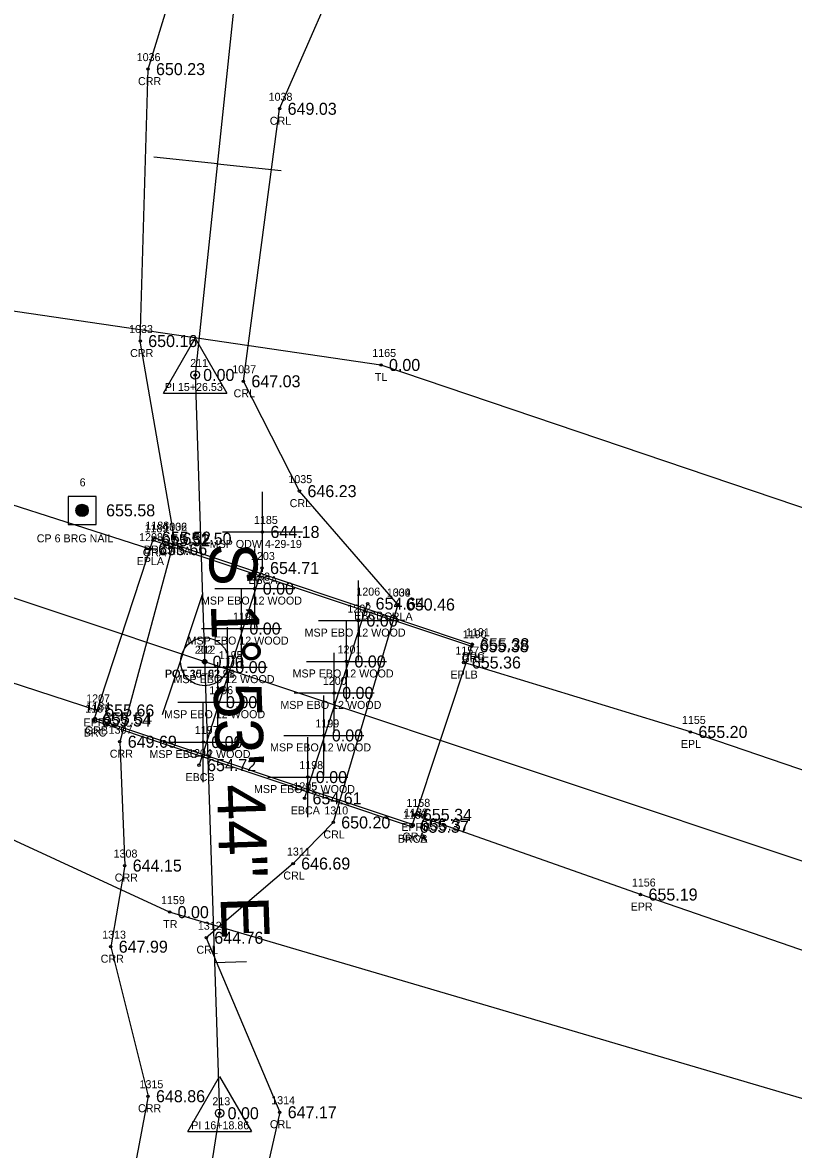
# Model space of a CAD drawing. Extents: x 1655137 to 1657928, y 1003994 to 1005407.
# Drawn here: x 1656349.2 to 1656445.6, y 1004565 to 1004705.8 of the extents above; entities that cross this region are included whole.
import ezdxf

# ---------------------------------------------------------------- set-up
doc = ezdxf.new("R2010")
doc.units = 0
for name, color, linetype in [('RD_EX_Bridge', 7, 'Continuous'), ('RD_EX_Bridge_txCode', 7, 'Continuous'), ('RD_EX_GuardRail', 7, 'Continuous'), ('RD_EX_GuardRail_txCode', 7, 'Continuous'), ('RD_EX_H2O', 7, 'Continuous'), ('RD_EX_H2O_txCode', 7, 'Continuous'), ('RD_EX_Road', 7, 'Continuous'), ('RD_EX_Road_txCode', 7, 'Continuous'), ('RD_EX_TX_Bridge_ELEV', 7, 'Continuous'), ('RD_EX_TX_GuardRail_ELEV', 7, 'Continuous'), ('RD_EX_TX_H2O_ELEV', 7, 'Continuous'), ('RD_EX_TX_Misc_ELEV', 7, 'Continuous'), ('RD_EX_TX_Road_ELEV', 7, 'Continuous'), ('RD_EX_TX_VEG_ELEV', 7, 'Continuous'), ('RD_EX_VEG', 7, 'Continuous'), ('RD_EX_VEG_txCode', 7, 'Continuous'), ('RD_HC_Cl', 7, 'Continuous'), ('RD_HC_Data', 7, 'Continuous'), ('RD_HC_Data_Tic', 7, 'Continuous'), ('RD_HC_Survey', 7, 'Continuous'), ('RD_HC_Survey_ELEV', 7, 'Continuous'), ('RD_HC_Survey_txCode', 7, 'Continuous'), ('RD_HC_txCode', 7, 'Continuous'), ('RD_SMD_Locator', 7, 'Continuous')]:
    doc.layers.add(name, color=color, linetype=linetype)

msp = doc.modelspace()

# ---------------------------------------------------------------- linework, layer by layer
at = {"layer": 'RD_EX_Bridge'}
for p, q in [((1656378.2, 1004630.06), (1656378.2, 1004640.06)), ((1656379.11, 1004637.63), (1656371.24, 1004612.99)), ((1656391.16, 1004626.06), (1656391.16, 1004636.06)), ((1656373.2, 1004635.06), (1656383.2, 1004635.06)), ((1656376.53, 1004625.06), (1656376.53, 1004635.06)), ((1656384.42, 1004608.84), (1656392.31, 1004633.18)), ((1656374.77, 1004620.24), (1656374.77, 1004630.24)), ((1656386.16, 1004631.06), (1656396.16, 1004631.06)), ((1656389.66, 1004620.95), (1656389.66, 1004630.95)), ((1656371.53, 1004630.06), (1656381.53, 1004630.06)), ((1656373.6, 1004615.86), (1656373.6, 1004625.86)), ((1656384.66, 1004625.95), (1656394.66, 1004625.95)), ((1656388.13, 1004617.02), (1656388.13, 1004627.02)), ((1656369.77, 1004625.24), (1656379.77, 1004625.24)), ((1656383.13, 1004622.02), (1656393.13, 1004622.02)), ((1656386.84, 1004611.71), (1656386.84, 1004621.71)), ((1656368.6, 1004620.86), (1656378.6, 1004620.86)), ((1656371.76, 1004610.88), (1656371.76, 1004620.88)), ((1656381.84, 1004616.71), (1656391.84, 1004616.71)), ((1656384.83, 1004606.5), (1656384.83, 1004616.5)), ((1656366.76, 1004615.88), (1656376.76, 1004615.88)), ((1656379.83, 1004611.5), (1656389.83, 1004611.5))]:
    msp.add_line(p, q, dxfattribs=at)
msp.add_lwpolyline([(1656397.81, 1004605.29), (1656358.07, 1004618.57), (1656365.58, 1004641.43), (1656405.39, 1004628.11), (1656397.81, 1004605.29)], dxfattribs=at)
for centre in [(1656378.2, 1004635.06), (1656376.53, 1004630.06), (1656391.16, 1004631.06), (1656389.66, 1004625.95), (1656374.77, 1004625.24), (1656388.13, 1004622.02), (1656373.6, 1004620.86), (1656371.76, 1004615.88), (1656386.84, 1004616.71), (1656384.83, 1004611.5)]:
    msp.add_circle(centre, 0.15, dxfattribs=at)
at = {"layer": 'RD_EX_GuardRail'}
for p, q in [((1656365.47, 1004641.1), (1656405.31, 1004627.86)), ((1656397.94, 1004605.56), (1656358.22, 1004618.83))]:
    msp.add_line(p, q, dxfattribs=at)
at = {"layer": 'RD_EX_H2O'}
for p, q in [((1656379.16, 1004637.14), (1656379.16, 1004647.14)), ((1656374.16, 1004642.14), (1656384.16, 1004642.14))]:
    msp.add_line(p, q, dxfattribs=at)
for points in [[(1656396.09, 1004633.07), (1656383.79, 1004647.24), (1656376.78, 1004660.97), (1656381.31, 1004695.03), (1656390.77, 1004716.64), (1656386.6, 1004756.66), (1656392.47, 1004790.44), (1656395.46, 1004834.73), (1656418.17, 1004880.53), (1656428.48, 1004936.46), (1656416.99, 1004968.14), (1656420.24, 1005011.82), (1656412.2, 1005039.74), (1656428.37, 1005086.9), (1656442.1, 1005137.22), (1656437.49, 1005175.75)], [(1656368.16, 1004641.29), (1656363.88, 1004666), (1656364.85, 1004699.99), (1656373.08, 1004726.71), (1656370.55, 1004754.49), (1656376.9, 1004793.18), (1656381.94, 1004832.3), (1656396.67, 1004890.43), (1656408.46, 1004936.92), (1656401.87, 1004961.79), (1656402.89, 1005007.98), (1656396.57, 1005037.78), (1656403.09, 1005084.85)], [(1656368.16, 1004641.29), (1656361.32, 1004615.92), (1656361.94, 1004600.44), (1656360.19, 1004590.3), (1656364.85, 1004571.61), (1656358.83, 1004539.66), (1656356.39, 1004495.48), (1656374.15, 1004488.29), (1656360.29, 1004470.44), (1656342.68, 1004443.17), (1656328, 1004380.72), (1656370, 1004347.54), (1656371.38, 1004313.92), (1656341.06, 1004297.9), (1656327.33, 1004287.25), (1656316.16, 1004265.33), (1656323.68, 1004217.95), (1656315.99, 1004185.06), (1656305.45, 1004150.63), (1656296.74, 1004101.67)], [(1656396.09, 1004633.07), (1656388.01, 1004605.83), (1656383, 1004600.69), (1656372.14, 1004591.42), (1656381.32, 1004569.61), (1656373.51, 1004535.02), (1656369.64, 1004512.2), (1656394.86, 1004499.5), (1656391.61, 1004464.63), (1656362.04, 1004437.06), (1656349.14, 1004389.09), (1656389.79, 1004361.99), (1656392.68, 1004307.58), (1656360.76, 1004281.14), (1656349.55, 1004259.28), (1656348.46, 1004221.09), (1656343.48, 1004177.61), (1656328.72, 1004142.77), (1656319.4, 1004085.87)]]:
    msp.add_lwpolyline(points, dxfattribs=at)
msp.add_circle((1656379.16, 1004642.14), 0.15, dxfattribs=at)
at = {"layer": 'RD_EX_Road'}
for points in [[(1656365.12, 1004639.99), (1656336.04, 1004649.34), (1656302.55, 1004660.37), (1656279.15, 1004668.23), (1656240.07, 1004681.05), (1656188.23, 1004698.03), (1656166.72, 1004705.51), (1656141.16, 1004714.06), (1656093.11, 1004730.11), (1656044.16, 1004746.75), (1655996.36, 1004762.45), (1655947.2, 1004778.68), (1655899.09, 1004794.03), (1655850.62, 1004809.99), (1655801.91, 1004826.1), (1655753.09, 1004842.31), (1655704.25, 1004858.1)], [(1656358.5, 1004619.83), (1656328.78, 1004629.48), (1656280.77, 1004645.39), (1656247.66, 1004656.11), (1656244.5, 1004656.52), (1656222.03, 1004663.57), (1656217.65, 1004665.96), (1656183.42, 1004677.32), (1656134.59, 1004693.72), (1656086.19, 1004709.75), (1656037.58, 1004726.13), (1655989.57, 1004741.99), (1655940.62, 1004757.88), (1655892.37, 1004773.61), (1655843.48, 1004789.36), (1655805.73, 1004801.4), (1655779.22, 1004810.43), (1655768.8, 1004813.1), (1655744.59, 1004822.13), (1655698.83, 1004837.65)], [(1657064.39, 1004409.09), (1657015.67, 1004424.64), (1656965.82, 1004440.6), (1656917.99, 1004455.95), (1656868.5, 1004471.86), (1656826.53, 1004486.06), (1656801.74, 1004494.51), (1656772.14, 1004504.27), (1656723.45, 1004520.92), (1656674.94, 1004537.34), (1656626.5, 1004553.88), (1656578.27, 1004569.52), (1656529.18, 1004584.75), (1656481.5, 1004600.51), (1656432.67, 1004617.14), (1656404.34, 1004625.82)], [(1657057.77, 1004388.92), (1657009.7, 1004404.08), (1656958.18, 1004419.84), (1656956.49, 1004419.67), (1656924.83, 1004429.55), (1656916.51, 1004432.8), (1656911.19, 1004434.68), (1656862.46, 1004450.21), (1656813.53, 1004466.42), (1656765.51, 1004482.33), (1656716.81, 1004499.14), (1656668.6, 1004515.93), (1656620.24, 1004532.54), (1656571.72, 1004548.37), (1656523.3, 1004563.77), (1656474.37, 1004580.29), (1656426.43, 1004596.82), (1656398.22, 1004606.78)]]:
    msp.add_lwpolyline(points, dxfattribs=at)
at = {"layer": 'RD_EX_VEG'}
for points in [[(1656290.27, 1004704.93), (1656304.88, 1004691.04), (1656300.23, 1004676.78), (1656393.98, 1004663.01), (1656541.61, 1004613.06), (1656540.34, 1004645.89)], [(1656891.08, 1004405.37), (1656915.13, 1004420.4), (1656763.49, 1004475.48), (1656570, 1004542.2), (1656467.82, 1004565.09), (1656367.55, 1004594.62), (1656280.9, 1004634.63), (1656273.57, 1004608.65)]]:
    msp.add_lwpolyline(points, dxfattribs=at)
at = {"layer": 'RD_HC_Cl'}
for p, q in [((1656388.64, 1004832.07), (1656370.75, 1004661.76)), ((1656069.26, 1004726.84), (1656507.36, 1004580.77)), ((1656370.75, 1004661.76), (1656373.8, 1004569.48)), ((1656373.8, 1004569.48), (1656363.49, 1004503.75))]:
    msp.add_line(p, q, dxfattribs=at)
at = {"layer": 'RD_HC_Data'}
for p, q in [((1656366.78, 1004659.47), (1656370.75, 1004666.35)), ((1656370.75, 1004666.35), (1656374.72, 1004659.47)), ((1656366.78, 1004659.47), (1656374.72, 1004659.47)), ((1656369.83, 1004567.19), (1656373.8, 1004574.07)), ((1656373.8, 1004574.07), (1656377.77, 1004567.19)), ((1656369.83, 1004567.19), (1656377.77, 1004567.19))]:
    msp.add_line(p, q, dxfattribs=at)
for centre, radius in [((1656370.75, 1004661.76), 0.529), ((1656371.93, 1004625.92), 3), ((1656371.93, 1004625.92), 3), ((1656371.93, 1004625.92), 0.282), ((1656371.93, 1004625.92), 0.282), ((1656373.8, 1004569.48), 0.529)]:
    msp.add_circle(centre, radius, dxfattribs=at)
at = {"layer": 'RD_HC_Data_Tic'}
for p, q in [((1656373.52, 1004688.14), (1656365.56, 1004688.98)), ((1656373.52, 1004688.14), (1656381.48, 1004687.31)), ((1656369.17, 1004626.84), (1656371.7, 1004634.43)), ((1656369.17, 1004626.84), (1656366.64, 1004619.26)), ((1656373.18, 1004588.33), (1656377.18, 1004588.46))]:
    msp.add_line(p, q, dxfattribs=at)
at = {"layer": 'RD_HC_Survey'}
for p, q in [((1656356.38, 1004644.1), (1656356.38, 1004645.57)), ((1656356.4, 1004644.1), (1656356.4, 1004645.58)), ((1656356.43, 1004644.09), (1656356.43, 1004645.59)), ((1656356.45, 1004644.08), (1656356.45, 1004645.59)), ((1656356.48, 1004644.08), (1656356.48, 1004645.6)), ((1656356.5, 1004644.08), (1656356.5, 1004645.6)), ((1656356.53, 1004644.07), (1656356.53, 1004645.6)), ((1656356.55, 1004644.07), (1656356.55, 1004645.61)), ((1656356.57, 1004644.07), (1656356.57, 1004645.61)), ((1656356.6, 1004644.07), (1656356.6, 1004645.61)), ((1656356.62, 1004644.07), (1656356.62, 1004645.61)), ((1656356.65, 1004644.07), (1656356.65, 1004645.61)), ((1656356.67, 1004644.07), (1656356.67, 1004645.6)), ((1656356.7, 1004644.07), (1656356.7, 1004645.6)), ((1656356.72, 1004644.08), (1656356.72, 1004645.6)), ((1656356.75, 1004644.08), (1656356.75, 1004645.59)), ((1656356.77, 1004644.09), (1656356.77, 1004645.59)), ((1656356.8, 1004644.09), (1656356.8, 1004645.58)), ((1656356.82, 1004644.1), (1656356.82, 1004645.58)), ((1656355.86, 1004644.66), (1656355.86, 1004645.02)), ((1656355.88, 1004644.58), (1656355.88, 1004645.1)), ((1656355.91, 1004644.52), (1656355.91, 1004645.16)), ((1656355.93, 1004644.47), (1656355.93, 1004645.21)), ((1656355.96, 1004644.43), (1656355.96, 1004645.25)), ((1656355.98, 1004644.39), (1656355.98, 1004645.29)), ((1656356.01, 1004644.36), (1656356.01, 1004645.32)), ((1656356.03, 1004644.33), (1656356.03, 1004645.35)), ((1656356.05, 1004644.3), (1656356.05, 1004645.38)), ((1656356.08, 1004644.28), (1656356.08, 1004645.4)), ((1656356.1, 1004644.25), (1656356.1, 1004645.42)), ((1656356.13, 1004644.23), (1656356.13, 1004645.44)), ((1656356.15, 1004644.21), (1656356.15, 1004645.46)), ((1656356.18, 1004644.2), (1656356.18, 1004645.48)), ((1656356.2, 1004644.18), (1656356.2, 1004645.49)), ((1656356.23, 1004644.17), (1656356.23, 1004645.51)), ((1656356.25, 1004644.15), (1656356.25, 1004645.52)), ((1656356.28, 1004644.14), (1656356.28, 1004645.53)), ((1656356.3, 1004644.13), (1656356.3, 1004645.55)), ((1656356.33, 1004644.12), (1656356.33, 1004645.56)), ((1656356.35, 1004644.11), (1656356.35, 1004645.56)), ((1656356.85, 1004644.11), (1656356.85, 1004645.57)), ((1656356.87, 1004644.12), (1656356.87, 1004645.56)), ((1656356.9, 1004644.13), (1656356.9, 1004645.55)), ((1656356.92, 1004644.14), (1656356.92, 1004645.54)), ((1656356.95, 1004644.15), (1656356.95, 1004645.53)), ((1656356.97, 1004644.16), (1656356.97, 1004645.52)), ((1656357, 1004644.17), (1656357, 1004645.5)), ((1656357.02, 1004644.19), (1656357.02, 1004645.49)), ((1656357.04, 1004644.21), (1656357.04, 1004645.47)), ((1656357.07, 1004644.22), (1656357.07, 1004645.45)), ((1656357.09, 1004644.24), (1656357.09, 1004645.43)), ((1656357.12, 1004644.27), (1656357.12, 1004645.41)), ((1656357.14, 1004644.29), (1656357.14, 1004645.39)), ((1656357.17, 1004644.31), (1656357.17, 1004645.36)), ((1656357.19, 1004644.34), (1656357.19, 1004645.33)), ((1656357.22, 1004644.37), (1656357.22, 1004645.3)), ((1656357.24, 1004644.41), (1656357.24, 1004645.27)), ((1656357.27, 1004644.45), (1656357.27, 1004645.23)), ((1656357.29, 1004644.49), (1656357.29, 1004645.18)), ((1656357.32, 1004644.55), (1656357.32, 1004645.13)), ((1656357.34, 1004644.62), (1656357.34, 1004645.06)), ((1656357.37, 1004644.73), (1656357.37, 1004644.95))]:
    msp.add_line(p, q, dxfattribs=at)
msp.add_lwpolyline([(1656358.36, 1004646.59), (1656354.86, 1004646.59), (1656354.86, 1004643.09), (1656358.36, 1004643.09)], close=True, dxfattribs=at)
msp.add_circle((1656356.61, 1004644.84), 0.769, dxfattribs=at)
at = {"layer": 'RD_SMD_Locator'}
for centre in [(1656364.85, 1004699.99), (1656381.31, 1004695.03), (1656363.88, 1004666), (1656393.98, 1004663.01), (1656370.75, 1004661.76), (1656376.78, 1004660.97), (1656383.79, 1004647.24), (1656356.61, 1004644.84), (1656365.58, 1004641.43), (1656368.16, 1004641.29), (1656368.16, 1004641.29), (1656365.12, 1004639.99), (1656365.47, 1004641.1), (1656379.11, 1004637.63), (1656392.31, 1004633.18), (1656396.09, 1004633.07), (1656396.09, 1004633.07), (1656405.31, 1004627.86), (1656405.39, 1004628.11), (1656371.93, 1004625.92), (1656371.93, 1004625.92), (1656404.34, 1004625.82), (1656358.22, 1004618.83), (1656358.5, 1004619.83), (1656358.07, 1004618.57), (1656361.32, 1004615.92), (1656432.67, 1004617.14), (1656371.24, 1004612.99), (1656384.42, 1004608.84), (1656398.22, 1004606.78), (1656388.01, 1004605.83), (1656397.81, 1004605.29), (1656397.81, 1004605.29), (1656397.94, 1004605.56), (1656361.94, 1004600.44), (1656383, 1004600.69), (1656426.43, 1004596.82), (1656367.55, 1004594.62), (1656372.14, 1004591.42), (1656360.19, 1004590.3), (1656364.85, 1004571.61), (1656373.8, 1004569.48), (1656381.32, 1004569.61)]:
    msp.add_circle(centre, 0.15, dxfattribs=at)

# ---------------------------------------------------------------- texts
at = {"layer": 'RD_EX_Bridge_txCode'}
for s, p in [('1188', (1656364.52, 1004642.43)), ('BRC', (1656364.33, 1004639.43)), ('1203', (1656377.73, 1004638.63)), ('1193', (1656377.14, 1004636.06)), ('EBCA', (1656377.4, 1004635.63)), ('1206', (1656390.9, 1004634.18)), ('MSP EBO 12 WOOD', (1656371.47, 1004633.06)), ('1202', (1656389.78, 1004632.06)), ('1194', (1656375.47, 1004631.06)), ('EBCB', (1656390.61, 1004631.18)), ('1191', (1656404.61, 1004629.11)), ('MSP EBO 12 WOOD', (1656369.8, 1004628.06)), ('MSP EBO 12 WOOD', (1656384.43, 1004629.06)), ('1201', (1656388.56, 1004626.95)), ('1195', (1656373.7, 1004626.24)), ('BRC', (1656404.14, 1004626.11)), ('MSP EBO 12 WOOD', (1656382.93, 1004623.95)), ('MSP EBO 12 WOOD', (1656368.04, 1004623.24)), ('1200', (1656386.71, 1004623.02)), ('1196', (1656372.51, 1004621.86)), ('1187', (1656357.01, 1004619.57)), ('MSP EBO 12 WOOD', (1656381.4, 1004620.02)), ('MSP EBO 12 WOOD', (1656366.86, 1004618.86)), ('BRC', (1656356.82, 1004616.57)), ('1197', (1656370.7, 1004616.88)), ('1199', (1656385.78, 1004617.71)), ('MSP EBO 12 WOOD', (1656365.03, 1004613.88)), ('1204', (1656369.86, 1004613.99)), ('MSP EBO 12 WOOD', (1656380.11, 1004614.71)), ('1198', (1656383.77, 1004612.5)), ('EBCB', (1656369.54, 1004610.99)), ('MSP EBO 12 WOOD', (1656378.1, 1004609.5)), ('1205', (1656383.03, 1004609.84)), ('EBCA', (1656382.7, 1004606.84)), ('1186', (1656396.72, 1004606.29)), ('1192', (1656396.75, 1004606.29)), ('BRCA', (1656396.07, 1004603.29)), ('BRCB', (1656396.09, 1004603.29))]:
    msp.add_text(s, height=1, dxfattribs=at).set_placement(p)
at = {"layer": 'RD_EX_GuardRail_txCode'}
for s, p in [('1189', (1656364.41, 1004642.1)), ('GRA', (1656364.2, 1004639.1)), ('1190', (1656404.21, 1004628.86)), ('GRB', (1656404.06, 1004625.86)), ('1184', (1656357.15, 1004619.83)), ('GRB', (1656356.96, 1004616.83)), ('1183', (1656396.88, 1004606.56)), ('GRA', (1656396.67, 1004603.56))]:
    msp.add_text(s, height=1, dxfattribs=at).set_placement(p)
at = {"layer": 'RD_EX_H2O_txCode'}
for s, p in [('1036', (1656363.44, 1004700.99)), ('CRR', (1656363.6, 1004697.99)), ('1038', (1656379.93, 1004696.03)), ('CRL', (1656380.08, 1004693.03)), ('1033', (1656362.49, 1004667)), ('CRR', (1656362.62, 1004664)), ('1037', (1656375.39, 1004661.97)), ('CRL', (1656375.55, 1004658.97)), ('1035', (1656382.4, 1004648.24)), ('CRL', (1656382.56, 1004645.24)), ('1306', (1656366.75, 1004642.29)), ('1032', (1656366.77, 1004642.29)), ('1185', (1656378.1, 1004643.14)), ('CRRA', (1656366.42, 1004639.29)), ('CRRA', (1656366.42, 1004639.29)), ('MSP ODW 4-29-19', (1656372.56, 1004640.14)), ('1034', (1656394.71, 1004634.07)), ('1309', (1656394.71, 1004634.07)), ('CRLA', (1656394.37, 1004631.07)), ('CRLA', (1656394.37, 1004631.07)), ('1307', (1656359.93, 1004616.92)), ('CRR', (1656360.07, 1004613.92)), ('1310', (1656386.9, 1004606.83)), ('CRL', (1656386.78, 1004603.83)), ('1308', (1656360.55, 1004601.44)), ('1311', (1656382.22, 1004601.69)), ('CRR', (1656360.69, 1004598.44)), ('CRL', (1656381.77, 1004598.69)), ('1313', (1656359.12, 1004591.3)), ('1312', (1656371.08, 1004592.42)), ('CRR', (1656358.93, 1004588.3)), ('CRL', (1656370.91, 1004589.42)), ('1315', (1656363.79, 1004572.61)), ('1314', (1656380.26, 1004570.61)), ('CRR', (1656363.6, 1004569.61)), ('CRL', (1656380.09, 1004567.61))]:
    msp.add_text(s, height=1, dxfattribs=at).set_placement(p)
at = {"layer": 'RD_EX_Road_txCode'}
for s, p in [('1208', (1656363.74, 1004640.99)), ('EPLA', (1656363.43, 1004637.99)), ('1157', (1656403.28, 1004626.82)), ('EPLB', (1656402.66, 1004623.82)), ('1207', (1656357.12, 1004620.83)), ('EPRA', (1656356.79, 1004617.83)), ('1155', (1656431.61, 1004618.14)), ('EPL', (1656431.47, 1004615.14)), ('1158', (1656397.16, 1004607.78)), ('EPRB', (1656396.52, 1004604.78)), ('1156', (1656425.35, 1004597.82)), ('EPR', (1656425.2, 1004594.82))]:
    msp.add_text(s, height=1, dxfattribs=at).set_placement(p)
at = {"layer": 'RD_EX_TX_Bridge_ELEV'}
for s, p in [('655.52', (1656366.58, 1004640.68)), ('654.71', (1656380.11, 1004636.88)), ('654.64', (1656393.31, 1004632.43)), ('655.38', (1656406.39, 1004627.36)), ('655.54', (1656359.07, 1004617.82)), ('654.72', (1656372.24, 1004612.24)), ('654.61', (1656385.42, 1004608.09)), ('655.37', (1656398.81, 1004604.54)), ('655.37', (1656398.81, 1004604.54))]:
    msp.add_text(s, height=1.5, dxfattribs=at).set_placement(p)
at = {"layer": 'RD_EX_TX_GuardRail_ELEV'}
for s, p in [('655.52', (1656366.47, 1004640.35)), ('655.38', (1656406.31, 1004627.11)), ('655.54', (1656359.22, 1004618.08)), ('655.37', (1656398.94, 1004604.81))]:
    msp.add_text(s, height=1.5, dxfattribs=at).set_placement(p)
at = {"layer": 'RD_EX_TX_H2O_ELEV'}
for s, p in [('650.23', (1656365.85, 1004699.24)), ('649.03', (1656382.31, 1004694.28)), ('650.16', (1656364.88, 1004665.25)), ('647.03', (1656377.78, 1004660.22)), ('646.23', (1656384.79, 1004646.49)), ('651.50', (1656369.16, 1004640.54)), ('651.50', (1656369.16, 1004640.54)), ('650.46', (1656397.09, 1004632.32)), ('650.46', (1656397.09, 1004632.32)), ('649.69', (1656362.32, 1004615.17)), ('650.20', (1656389.01, 1004605.08)), ('644.15', (1656362.94, 1004599.69)), ('646.69', (1656384, 1004599.94)), ('644.76', (1656373.14, 1004590.67)), ('647.99', (1656361.19, 1004589.55)), ('648.86', (1656365.85, 1004570.86)), ('647.17', (1656382.32, 1004568.86))]:
    msp.add_text(s, height=1.5, dxfattribs=at).set_placement(p)
at = {"layer": 'RD_EX_TX_Misc_ELEV'}
for s, p in [('644.18', (1656380.16, 1004641.39)), ('0.00', (1656379.2, 1004634.31)), ('0.00', (1656392.16, 1004630.31)), ('0.00', (1656377.53, 1004629.31)), ('0.00', (1656375.77, 1004624.49)), ('0.00', (1656390.66, 1004625.2)), ('0.00', (1656374.6, 1004620.11)), ('0.00', (1656389.13, 1004621.27)), ('0.00', (1656387.84, 1004615.96)), ('0.00', (1656372.76, 1004615.13)), ('0.00', (1656385.83, 1004610.75))]:
    msp.add_text(s, height=1.5, dxfattribs=at).set_placement(p)
at = {"layer": 'RD_EX_TX_Road_ELEV'}
for s, p in [('655.66', (1656366.12, 1004639.24)), ('655.36', (1656405.34, 1004625.07)), ('655.66', (1656359.5, 1004619.08)), ('655.20', (1656433.67, 1004616.39)), ('655.34', (1656399.22, 1004606.03)), ('655.19', (1656427.43, 1004596.07))]:
    msp.add_text(s, height=1.5, dxfattribs=at).set_placement(p)
at = {"layer": 'RD_EX_TX_VEG_ELEV'}
for p in [(1656394.98, 1004662.26), (1656368.55, 1004593.87)]:
    msp.add_text('0.00', height=1.5, dxfattribs=at).set_placement(p)
at = {"layer": 'RD_EX_VEG_txCode'}
for s, p in [('1165', (1656392.89, 1004664.01)), ('TL', (1656393.21, 1004661.01)), ('1159', (1656366.48, 1004595.62)), ('TR', (1656366.75, 1004592.62))]:
    msp.add_text(s, height=1, dxfattribs=at).set_placement(p)
at = {"layer": 'RD_HC_Data'}
msp.add_text('S 1%%d 53\' 44" E', height=6, rotation=271.8955, dxfattribs=at).set_placement((1656372.45, 1004640.68))
at = {"layer": 'RD_HC_Survey_ELEV'}
for s, p in [('0.00', (1656371.75, 1004661.01)), ('655.58', (1656359.61, 1004644.09)), ('0.00', (1656372.93, 1004625.17)), ('0.00', (1656372.93, 1004625.17)), ('0.00', (1656374.8, 1004568.73))]:
    msp.add_text(s, height=1.5, dxfattribs=at).set_placement(p)
at = {"layer": 'RD_HC_Survey_txCode'}
for s, p in [('6', (1656356.3, 1004647.84)), ('CP 6 BRG NAIL', (1656350.94, 1004640.84))]:
    msp.add_text(s, height=1, dxfattribs=at).set_placement(p)
at = {"layer": 'RD_HC_txCode'}
for s, p in [('211', (1656370.13, 1004662.76)), ('PI 15+26.53', (1656366.95, 1004659.76)), ('202', (1656370.71, 1004626.92)), ('212', (1656371.04, 1004626.92)), ('POT 30+02.91', (1656366.94, 1004623.92)), ('POT 15+62.38', (1656367, 1004623.92)), ('213', (1656372.9, 1004570.48)), ('PI 16+18.86', (1656370.26, 1004567.48))]:
    msp.add_text(s, height=1, dxfattribs=at).set_placement(p)

doc.saveas('drawing.dxf')
